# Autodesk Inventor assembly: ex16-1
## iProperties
Shininess: 64.0
Length Units: 11269
Angle Units: 11279
Time Units: 11290
Mass Units: 11283
Length Display Precision: 3
Angle Display Precision: 2
Compacted: True
Created: 2002-11
Part Number: ex16-1
Document SubType Name: Assembly
Designer: E. MOSS
Density: 0.0
Volumn: 0.0
Area: 0.0
PropertySet Name: Model Information
Control State: 0
Master: False
Checked Out: False
Author: E. MOSS
